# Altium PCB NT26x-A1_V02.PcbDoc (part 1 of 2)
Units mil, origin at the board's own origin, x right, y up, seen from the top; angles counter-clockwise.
Board outline 1026.77 x 2401.57 mil, 4 copper layers (Top Layer 1, GND2, POWER3, Bottom Layer 4), stack 61.855 mil thick; 87 components, 81 nets, 679 pads, 247 vias.
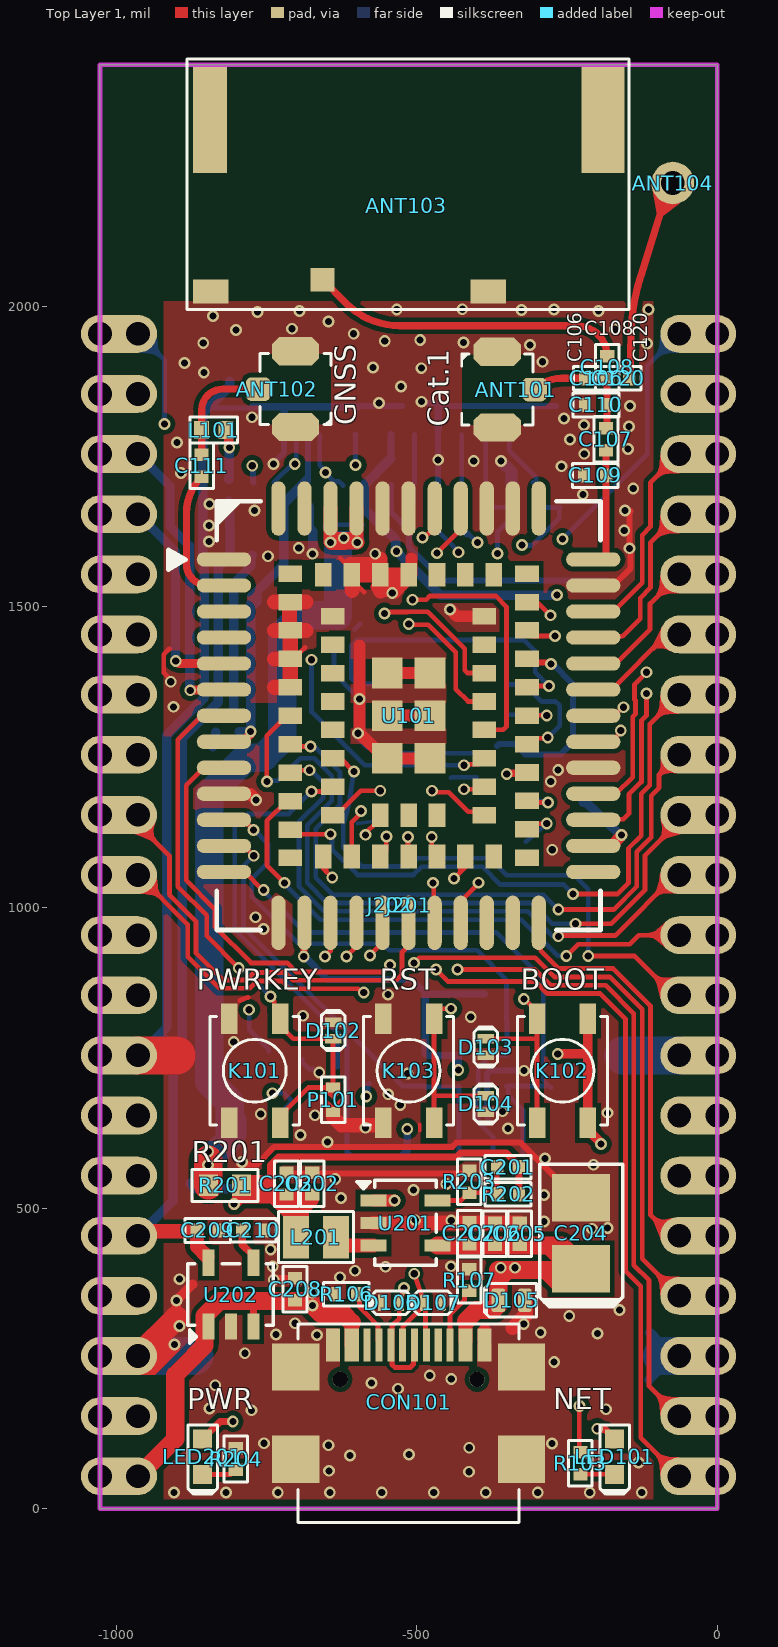
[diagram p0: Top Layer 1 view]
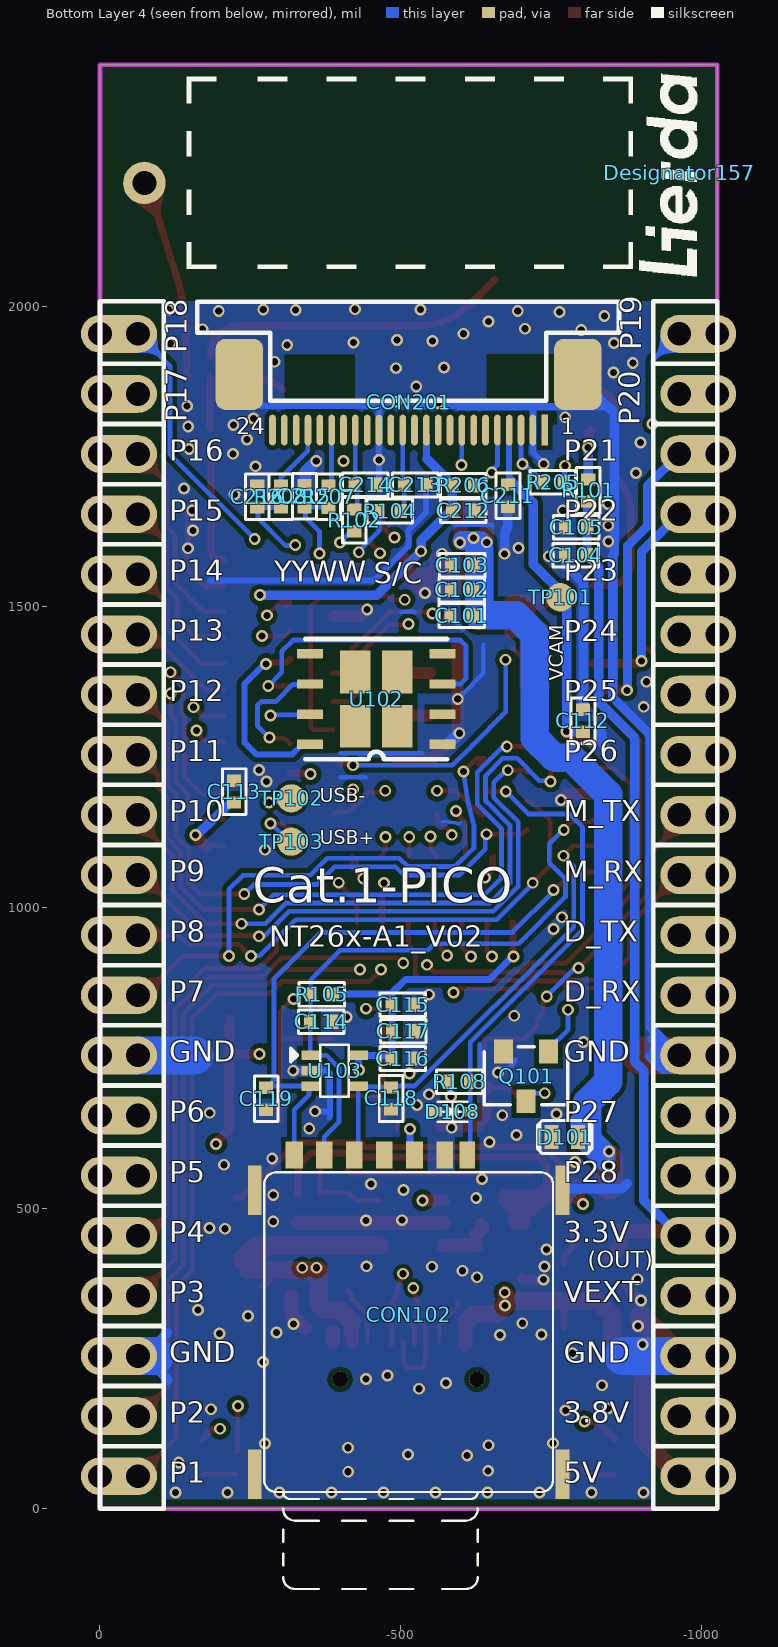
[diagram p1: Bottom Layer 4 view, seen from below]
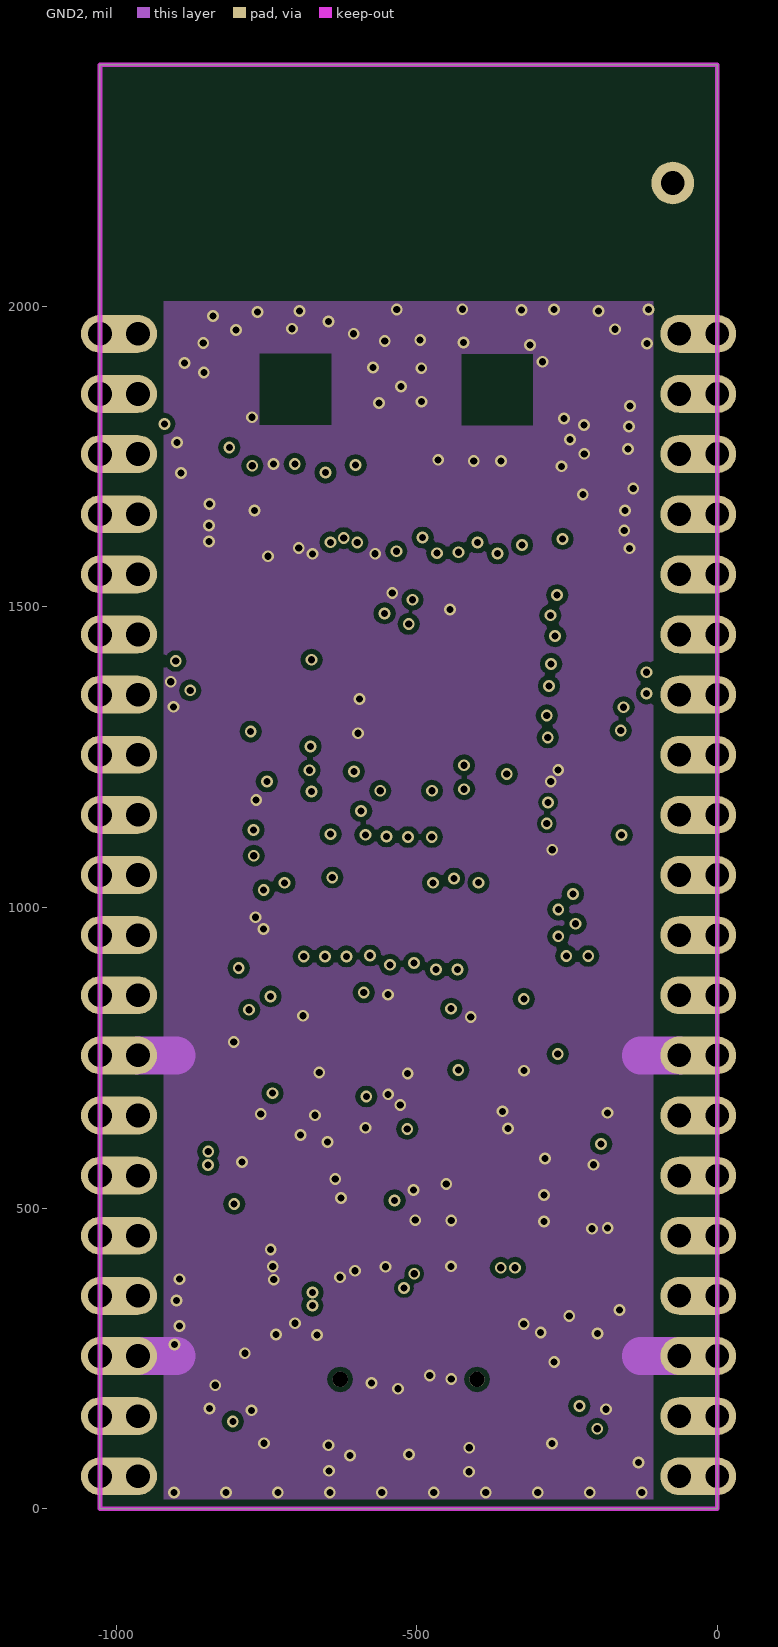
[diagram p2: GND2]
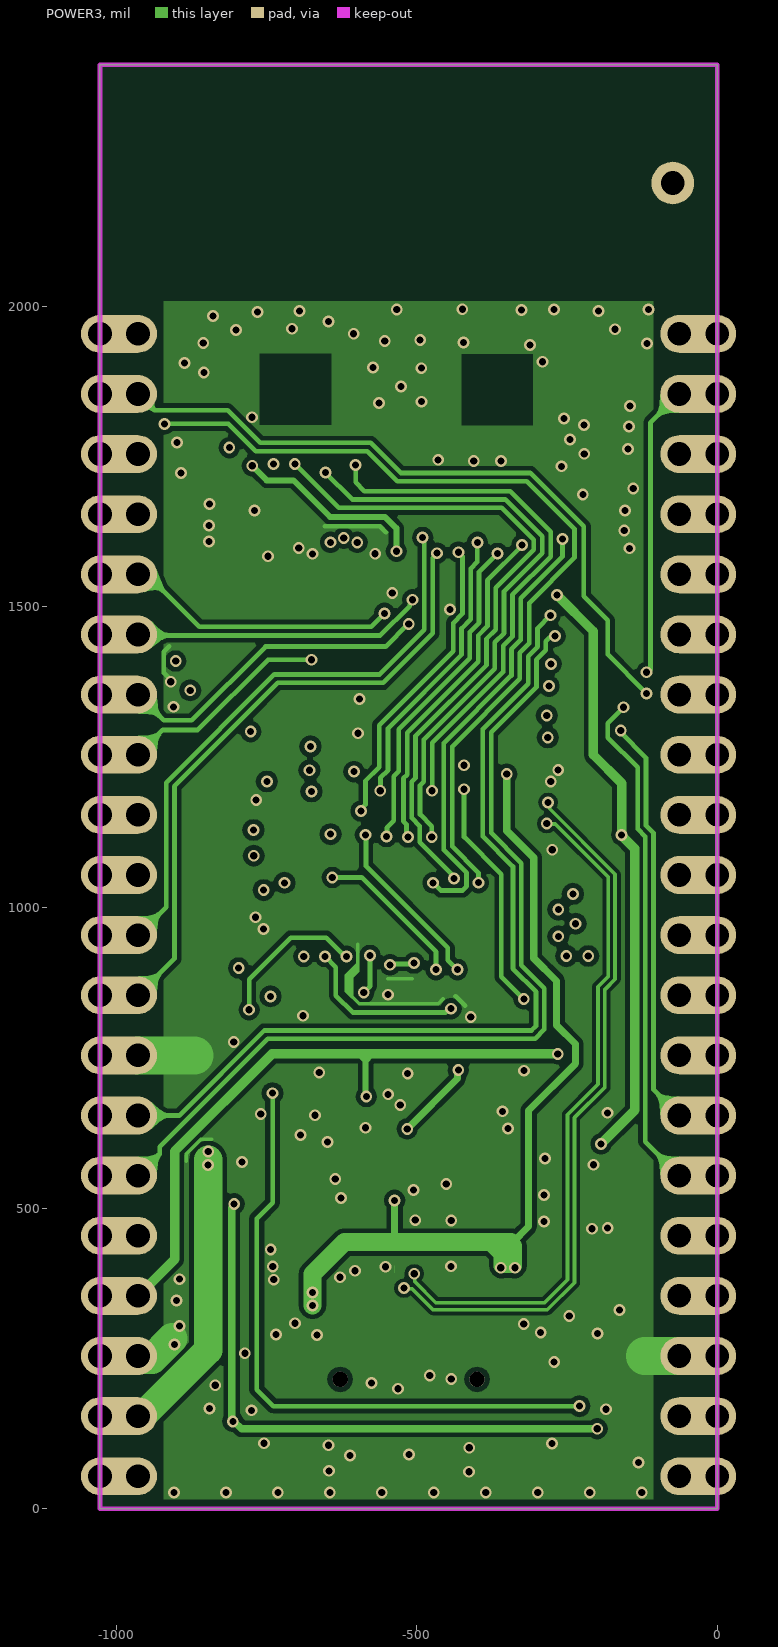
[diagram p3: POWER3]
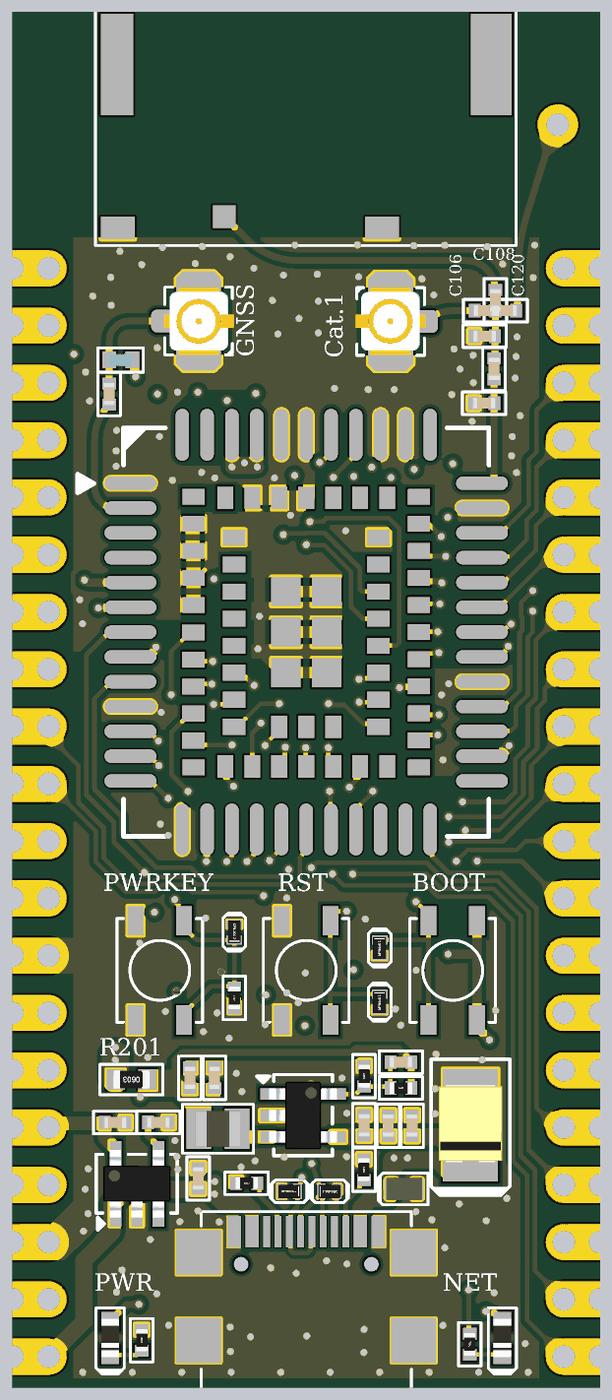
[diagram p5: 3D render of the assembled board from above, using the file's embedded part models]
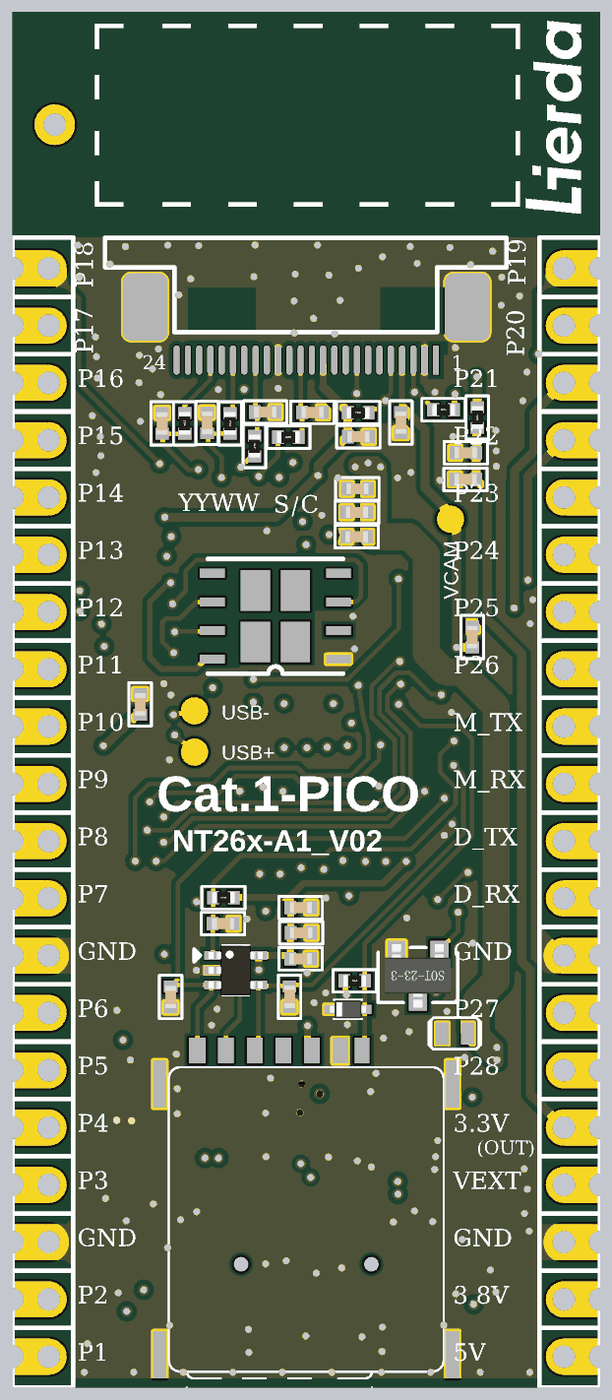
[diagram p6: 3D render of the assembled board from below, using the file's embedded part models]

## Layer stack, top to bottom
Top Solder: solder mask 0.4, Solder Resist, Dk 3.5
Top Layer 1: signal copper 1.378
Dielectric 2: prepreg 8.4646, PP-006, Dk 4.1
GND2: signal copper 1.4
Dielectric 1: dielectric 39.3701, FR-4, Dk 4.8
POWER3: signal copper 1.4
Dielectric 3: prepreg 8.4646, PP-006, Dk 4.1
Bottom Layer 4: signal copper 1.378
Bottom Solder: solder mask 0.4, Solder Resist, Dk 3.5

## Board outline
0,2401.57 -1026.77,2401.57 -1026.77,0 0,0

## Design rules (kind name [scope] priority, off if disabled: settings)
Clearance Clearance_RF [InNetClass('RF')] p1: gap=8 ignorepadtopadclearanceinfootprint=FALSE
Clearance Clearance_diff [InDifferentialPair('usb')] p2: gap=5.5 ignorepadtopadclearanceinfootprint=FALSE except(6: Arc-Fill Arc-Poly Arc-Region Track-Fill Track-Poly Track-Region SMDPad-Fill SMDPad-Poly SMDPad-Region THPad-Fill THPad-Poly THPad-Region Via-Fill Via-Poly Via-Region Fill-Fill Fill-Poly Fill-Region Poly-Poly Poly-Region Region-Region)
Clearance Clearance_via [IsVia vs IsVia] p3: gap=15.75 ignorepadtopadclearanceinfootprint=FALSE
Clearance Clearance_keepout [IsKeepOut] p4: gap=11.81 ignorepadtopadclearanceinfootprint=FALSE
Clearance Clearance_polygon [InPolygon] p5: gap=8 ignorepadtopadclearanceinfootprint=FALSE
Clearance [All] p6: gap=5.98 ignorepadtopadclearanceinfootprint=FALSE except(8: Arc-Fill Arc-Poly Arc-Region Track-Fill Track-Poly Track-Region SMDPad-Fill SMDPad-Poly SMDPad-Region THPad-Fill THPad-Poly THPad-Region Via-Fill Via-Poly Via-Region Fill-Fill Fill-Poly Fill-Region Poly-Poly Poly-Region Region-Region)
DiffPairsRouting [All] p1: maxlimit=5.5 minlimit=5.5 mostfreqgap=5.5 toplayer_minwidth=8 toplayer_maxwidth=8 toplayer_prefwidth=8 midlayer1_minwidth=6 midlayer1_maxwidth=6 midlayer1_prefwidth=6 midlayer2_minwidth=6 midlayer2_maxwidth=6 midlayer2_prefwidth=6 bottomlayer_minwidth=8 bottomlayer_maxwidth=8 bottomlayer_prefwidth=8 maxuncoupledlength=500
HoleSize [All] p1: absolutevalues=TRUE maxlimit=196.85 minlimit=1 maxpercent=80.000 minpercent=20.000
HoleToHoleClearance [All] p1: gap=0 allowstackedmicrovias=TRUE
MinimumSolderMaskSliver [All] p1: minsoldermaskwidth=0
PolygonConnect [All] p1: thpad.connectstyle=Relief thpad.reliefconductorwidth=15 thpad.reliefentries=4 thpad.polygonreliefangle="90 Angle" thpad.airgapwidth=10 smdpad.connectstyle=Direct smdpad.reliefconductorwidth=10 smdpad.reliefentries=4 smdpad.polygonreliefangle="90 Angle" smdpad.airgapwidth=10 via.connectstyle=Direct via.reliefconductorwidth=10 via.reliefentries=4 via.polygonreliefangle="90 Angle" via.airgapwidth=10
RoutingVias [All] p1: holewidth=11.81 width=19.68 viastyle="Through Hole" minholewidth=11.81 minwidth=19.68 maxholewidth=118.11 maxwidth=196.85
SilkToSilkClearance [All] p1: silktosilkclearance=0
SilkToSolderMaskClearance [IsPad] p1: minsilkscreentomaskgap=0 clearancetoexposedcopper=TRUE
SolderMaskExpansion [All] p1: expansion=4
Width [All] p1: maxlimit=196.85 minlimit=5.98 preferedwidth=10
24 further rules are at their usual default settings.

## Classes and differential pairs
net class CAM: CAM_I2C_SCL CAM_I2C_SDA CAM_MCLK CAM_PWDN CAM_SPI_CLK CAM_SPI_D0 CAM_SPI_D1
net class RF: NetANT101_1 NetANT102_1 NetANT103_1 NetANT104_1 NetC106_1 NetC107_2 NetC111_2
component class 02_Peripheral: C201 C202 C203 C204 C205 C206 C207 C208 C209 C210 C211 C212 C213 C214 C215 C216 CON201 J201 J202 L201 LED201 R201 R202 R203 R204 R205 R206 R207 R208 U201 U202
component class 01_NT26FCNB30: ANT101 ANT102 ANT103 ANT104 C101 C102 C103 C104 C105 C106 C107 C108 C109 C110 C111 C112 C113 C114 C115 C116 C117 C118 C119 C120 CON101 CON102 D101 D102 D103 D104 D105 D106 D107 D108 K101 K102 K103 L101 LED101 P101 Q101 R101 R102 R103 R104 R105 R106 R107 R108 TP101 TP102 TP103 U101 U102 U103
differential pair usb: +USB_DN -USB_DP

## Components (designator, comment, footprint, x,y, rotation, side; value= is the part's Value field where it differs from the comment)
ANT101 "IPEX-1" IPX_U.FL-R-SMT-1 -366.35,1861.57 r180 top
ANT102 "IPEX-1" IPX_U.FL-R-SMT-1 -701.09,1861.57 r0 top
ANT103 "PCB天线" ANT -513.39,2201.56 r0 top locked
ANT104 "弹簧天线" ANT104 -74.02,2204.72 r270 top locked
C101 "10uF/10V" 0402C_0.4D -601.52,1485.43 r180 bottom
C102 "0.1uF" 0402C_0.4D -602.08,1528.05 r180 bottom
C103 "33pF" 0402C_0.4D -602.67,1568.98 r180 bottom
C104 "1uF/16V" 0402C_0.4D -791.64,1585.56 r180 bottom
C105 "100pF" 0402C_0.4D -792.1,1632.07 r180 bottom
C106 "NC" 0402C_0.4D -201.22,1879.99 r180 top
C107 "33pF" 0402C_0.4D -185.18,1778.35 r270 top
C108 "NC" 0402C_0.4D -183.02,1898.2 r270 top
C109 "NC" 0402C_0.4D -202.74,1718.44 r0 top
C110 "NC" 0402C_0.4D -201.78,1835.65 r0 top
C111 "33pF" 0402C_0.4D -857.58,1734.5 r270 top
C112 "1uF/16V" 0402C_0.4D -803.34,1310.21 r270 bottom
C113 "1uF/16V" 0402C_0.4D -223.24,1192.74 r270 bottom
C114 "33pF" 0402C_0.4D -368.1,809.93 r0 bottom
C115 "1uF/10V" 0402C_0.4D -503.84,838.01 r0 bottom
C116 "0.1uF" 0402C_0.4D -503.39,748.64 r0 bottom
C117 "33pF" 0402C_0.4D -504.44,793.9 r0 bottom
C118 "33pF" 0402C_0.4D -484.25,682.26 r90 bottom
C119 "33pF" 0402C_0.4D -276.42,681.79 r90 bottom
C120 "33pF" 0402C_0.4D -164.81,1879.99 r0 top
C201 "22pF" 0402C_0.4D -348.1,568.09 r0 top
C202 "0.1uF" 0402C_0.4D -673.72,540.72 r270 top
C203 "10uF/10V" 0402C_0.4D -716.6,540.72 r270 top
C204 "CAP-P" 3528-TB -226.46,457.94 r270 top
C205 "10uF/10V" 0402C_0.4D -328.56,457.23 r270 top
C206 "1uF/16V" 0402C_0.4D -369.91,457.23 r270 top
C207 "0.1uF" 0402C_0.4D -412.23,458 r270 top
C208 "1uF/16V" 0402C_0.4D -702.2,365.14 r270 top
C209 "1uF/16V" 0402C_0.4D -847.22,462.72 r180 top
C210 "0.01uF" 0402C_0.4D -771.78,462.86 r180 top
C211 "1uF" 0402C_0.4D -678.68,1684.65 r270 bottom
C212 "1uF" 0402C_0.4D -604.39,1659.93 r180 bottom
C213 "NC" 0402C_0.4D -524.33,1702.63 r0 bottom
C214 "NC" 0402C_0.4D -441.6,1703.07 r0 bottom
C215 "NC" 0402C_0.4D -340.12,1684.04 r270 bottom
C216 "NC" 0402C_0.4D -261.69,1683.3 r270 bottom
CON101 "USB-TYPE C-12P" "TYPEC _6PIN板" -513.39,177.17 r0 top locked
CON102 "nano-SIM卡座" SIM-MUP-C7801 -513.39,322.83 r180 bottom locked
CON201 "FPC-24" 0.5S-3S-24PWB -513.39,1840.17 r0 bottom locked
D101 "NC" UDFN2(1610)-NP -773.09,618.09 r0 bottom
D102 "TVS" DFN1006-NP#1 -638.96,795.31 r90 top
D103 "TVS" DFN1006-NP#1 -385.13,767.67 r270 top
D104 "TVS" DFN1006-NP#1 -385.13,673.12 r270 top
D105 "DIODE-TVS" UDFN2(1610) -342.12,346.69 r0 top
D106 "DIODE-2TVS-2" DFN1006-NP#1 -542.6,342.66 r180 top
D107 "DIODE-2TVS-2" DFN1006-NP#2 -472.71,342.49 r0 top
D108 "TVS/5V" SOD-523-NP -586.26,660.36 r180 bottom
Designator157 "Comment" LOGO -963.39,2221.57 r90 bottom
J201 "CON_PICO" J201_半孔与排针 -31.69,53.94 r180 top locked
J202 "CON_PICO" J202_半孔与排针 -1026.77,1953.94 r180 top locked
K101 "1414000735" TS3443-0253B -769.29,728.35 r90 top locked
K102 "1414000735" TS3443-0253B -257.48,728.35 r90 top locked
K103 "1414000735" TS3443-0253B -513.39,728.35 r90 top locked
L101 "56nH" 0402LX_0.4D -837.4,1793.92 r0 top
L201 "1uH" 0806L_0.6D -667.53,451.77 r180 top
LED101 "LED绿/25mA" D0603 -170.87,86.61 r90 top
LED201 "LED红/25mA" D0603 -855.91,86.61 r90 top
P101 "PWRKEY" 0402R_0.4D_JP -638.96,680.18 r270 top
Q101 "DTC143XCA" SOT-23-3A -708.63,719 r90 bottom
R101 "10R" 0402R_0.4D -812.28,1693.44 r270 bottom
R102 "22R" 0402R_0.4D -422.93,1643.58 r270 bottom
R103 "1K" 0402R_0.4D -227.75,75.7 r90 top
R104 "22R" 0402R_0.4D -482.21,1659.2 r0 bottom
R105 "NC" 0402R_0.4D -368.81,855.32 r180 bottom
R106 "5.1K" 0402R_0.4D -617.41,356.7 r0 top
R107 "5.1K" 0402R_0.4D -412.54,380.36 r270 top
R108 "NC" 0402R_0.4D -597.98,709.91 r180 bottom
R201 "0R" 0603R_0.6D -818.69,537.73 r180 top
R202 "118K" 0402R_0.4D -348.05,523.08 r0 top
R203 "22.1K" 0402R_0.4D -412.34,543.61 r90 top
R204 "1K" 0402R_0.4D -800.79,82.68 r90 top
R205 "4.7K" 0402R_0.4D -753.33,1706.98 r180 bottom
R206 "4.7K" 0402R_0.4D -604.21,1701.84 r0 bottom
R207 "22R" 0402R_0.4D -380.3,1683.1 r90 bottom
R208 "22R" 0402R_0.4D -300.97,1683.3 r90 bottom
TP101 "CAM_VDD" test#1 -765.46,1515.97 r270 bottom
TP102 "USB_DN" test#1 -318.2,1181.4 r180 bottom
TP103 "USB_DP" test#2 -304.88,1109.37 r180 bottom
U101 "NT26F Y0A-P" LSDWNTC-LY04095005_mood -513.39,1318.9 r0 top locked
U102 "NC" DFN8(1.27)-6X5 -459.64,1346.57 r0 bottom
U103 "NSQA6V8AW5T2G" SOT-323-5 -390.33,728.47 r0 bottom
U201 "ETA3417S2F" SOT-23-5P -518.8,475.08 r180 top
U202 "SGM2036-XYN5G/TR" SOT-23-5P -809.05,355.9 r270 top

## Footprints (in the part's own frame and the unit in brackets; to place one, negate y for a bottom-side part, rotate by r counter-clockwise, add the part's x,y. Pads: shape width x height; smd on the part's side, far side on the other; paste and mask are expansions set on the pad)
0.5S-3S-24PWB [mm]
  rrect40% 2x3 smd mask+0.075: 0(-7.15,-1.175) 0(7.15,-1.175)
  rect 0.28x1.3 smd mask+0.051: 1(-5.75,1.175)
  oval 0.28x1.3 smd mask+0.051: 2(-5.25,1.175) 3(-4.75,1.175) 4(-4.25,1.175) 5(-3.75,1.175) 6(-3.25,1.175) 7(-2.75,1.175) 8(-2.25,1.175) 9(-1.75,1.175) 10(-1.25,1.175) 11(-0.75,1.175) 12(-0.25,1.175) 13(0.25,1.175) 14(0.75,1.175) 15(1.25,1.175) 16(1.75,1.175) 17(2.25,1.175) 18(2.75,1.175) 19(3.25,1.175) 20(3.75,1.175) 21(4.25,1.175) 22(4.75,1.175) 23(5.25,1.175) 24(5.75,1.175)
  silkscreen extent -8.89,-4.24 8.93,-0.06, body extent -9.15,-4.07 9.15,0.63, height 2.05
0402C_0.4D [mm]
  rect 0.525x0.6 smd: 1(-0.463,0) 2(0.463,0)
  silkscreen extent -0.96,-0.5 0.96,0.5, body extent -0.5,-0.25 0.5,0.25, height 0.48
0402LX_0.4D [mm] "线绕电感"
  rect 0.625x0.75 smd: 1(-0.513,0) 2(0.513,0)
  Top Layer 1 pour cut-out: -0.2,-0.478 -0.2,0.478 0.2,0.478 0.2,-0.478
  silkscreen extent -1.01,-0.55 1,0.54, body extent -0.5,-0.3 0.5,0.3, height 0.51
0402R_0.4D [mm]
  rect 0.525x0.6 smd: 1(-0.463,0) 2(0.463,0)
  silkscreen extent -0.96,-0.5 0.96,0.5, body extent -0.5,-0.25 0.5,0.25, height 0.36
0402R_0.4D_JP [mm]
  rect 0.425x0.6 smd mask+0.05: 1(-0.513,0) 2(0.513,0)
  Top Layer 1 region: 0,0 -0.3,0.3 -0.725,0.3 -0.725,-0.3 -0.3,-0.3
  Top Layer 1 region: -0.05,0.3 0.25,0 -0.05,-0.3 0.725,-0.3 0.725,0.3
  silkscreen extent -0.96,-0.5 0.96,0.5, body extent -0.5,-0.25 0.5,0.25, height 0.36
0603R_0.6D [mm]
  rect 0.8x0.9 smd: 1(-0.7,0) 2(0.7,0)
  silkscreen extent -1.4,-0.67 1.4,0.67, body extent -0.8,-0.4 0.8,0.4, height 0.46
0806L_0.6D [mm]
  rect 1.1x1.8 smd: 1(-0.85,0) 2(0.85,0)
  Top Layer 1 pour cut-out: -0.3,-0.9 -0.3,0.9 0.301,0.9 0.301,-0.9
  silkscreen extent -1.58,-1.08 1.58,1.08, body extent -1,-0.8 1,0.8, height 1
3528-TB [mm]
  rect 2x2.45 smd: 1(1.5,0) 2(-1.5,0)
  silkscreen extent -2.93,-1.75 3.1,1.75, body extent -1.82,-1.4 1.67,1.4, height 1.91
ANT [mm]
  rect 1x1 smd: 1(-3.64,-4)
  rect 1.5x1 smd: 2(-8.36,-4.5) 2(3.36,-4.5)
  rect 1.43x4.5 smd: 3(-8.395,2.75)
  rect 1.8x4.5 smd: 4(8.21,2.75)
  silkscreen extent -9.35,-5.27 9.31,5.32
ANT104 [mm]
  round 1.8 hole 1: 1(0,0)
D0603 [mm]
  rect 0.8x0.8 smd: A(0.75,0) K(-0.75,0)
  silkscreen extent -1.59,-0.63 1.33,0.63, body extent -0.85,-0.4 0.85,0.4, height 0.56
DFN8(1.27)-6X5 [mm]
  rect 1.3x1.8 smd: 0(-0.889,-1.143) 0(-0.889,1.143) 0(0.889,-1.143) 0(0.889,1.143)
  rect 1.1x0.4 smd: 1(-2.8,1.905) 2(-2.8,0.635) 3(-2.8,-0.635) 4(-2.8,-1.905) 5(2.8,-1.905) 6(2.8,-0.635) 7(2.8,0.635) 8(2.8,1.905)
  round 0.3 on Mech15 mask+0: ""(-2.8,1.905)
  rect 0.6x0.4 on Mech1 mask+0: ""(-2.7,-1.905) ""(-2.7,-0.635) ""(-2.7,0.635) ""(-2.7,1.905) ""(2.7,-1.905) ""(2.7,-0.635) ""(2.7,0.635) ""(2.7,1.905)
  round 0.3 on Mech1 mask+0: ""(0,0) ""(0,0)
  rect 3.4x4.2 on Mech1 mask+0: ""(0,0)
  silkscreen extent -3,-2.54 3,2.54
DFN1006-NP#1 [mm]
  rect 0.4x0.7 smd mask+0.051: A(0.35,0) K(-0.35,0)
  rect 0.25x0.5 on Mech1: ""(-0.325,0) ""(0.325,0)
  silkscreen extent -0.85,-0.5 0.85,0.5, body extent -0.5,-0.3 0.5,0.3, height 0.51
DFN1006-NP#2 [mm]
  rrect40% 0.4x0.7 smd mask+0.051: A(0.35,0) K(-0.35,0)
  rect 0.25x0.5 on Mech1: ""(-0.325,0) ""(0.325,0)
  silkscreen extent -0.85,-0.5 0.85,0.5, body extent -0.5,-0.3 0.5,0.3, height 0.51
IPX_U.FL-R-SMT-1 [mm]
  rrect50% 1.05x1 smd: 1(-1.585,0.01)
  oct 2x1.2 smd: 2(-0.01,-1.59) 3(-0.01,1.61)
  Multi-Layer pour cut-out: 1.49,1.51 1.49,-1.49 -1.51,-1.49 -1.51,1.51
  silkscreen extent -1.51,-1.49 1.49,1.51, body extent -1.55,-1.5 1.55,1.5, height 1.25
J201_半孔与排针 [mm]
  round 1.6 hole 1: 1(-0.805,0) 1(0.805,0) 2(-0.805,-2.54) 2(0.805,-2.54) 3(-0.805,-5.08) 3(0.805,-5.08) 4(-0.805,-7.62) 4(0.805,-7.62) 5(-0.805,-10.16) 5(0.805,-10.16) 6(-0.805,-12.7) 6(0.805,-12.7) 7(-0.805,-15.24) 7(0.805,-15.24) 8(-0.805,-17.78) 8(0.805,-17.78) 9(-0.805,-20.32) 9(0.805,-20.32) 10(-0.805,-22.86) 10(0.805,-22.86) 11(-0.805,-25.4) 11(0.805,-25.4) 12(-0.805,-27.94) 12(0.805,-27.94) 13(-0.805,-30.48) 13(0.805,-30.48) 14(-0.805,-33.02) 14(0.805,-33.02) 15(-0.805,-35.56) 15(0.805,-35.56) 16(-0.805,-38.1) 16(0.805,-38.1) 17(-0.805,-40.64) 17(0.805,-40.64) 18(-0.805,-43.18) 18(0.805,-43.18) 19(-0.805,-45.72) 19(0.805,-45.72) 20(-0.805,-48.26) 20(0.805,-48.26)
  rect 1.6x1.6 all layers, no hole: 1(0,0) 2(0,-2.54) 3(0,-5.08) 4(0,-7.62) 5(0,-10.16) 6(0,-12.7) 7(0,-15.24) 8(0,-17.78) 9(0,-20.32) 10(0,-22.86) 11(0,-25.4) 12(0,-27.94) 13(0,-30.48) 14(0,-33.02) 15(0,-35.56) 16(0,-38.1) 17(0,-40.64) 18(0,-43.18) 19(0,-45.72) 20(0,-48.26)
  round 1.6 on Mech1: 21(23.665,-48.26) 21(25.275,-48.26) 22(23.665,-45.72) 22(25.275,-45.72) 23(23.665,-43.18) 23(25.275,-43.18) 24(23.665,-40.64) 24(25.275,-40.64) 25(23.665,-38.1) 25(25.275,-38.1) 26(23.665,-35.56) 26(25.275,-35.56) 27(23.665,-33.02) 27(25.275,-33.02) 28(23.665,-30.48) 28(25.275,-30.48) 29(23.665,-27.94) 29(25.275,-27.94) 30(23.665,-25.4) 30(25.275,-25.4) 31(23.665,-22.86) 31(25.275,-22.86) 32(23.665,-20.32) 32(25.275,-20.32) 33(23.665,-17.78) 33(25.275,-17.78) 34(23.665,-15.24) 34(25.275,-15.24) 35(23.665,-12.7) 35(25.275,-12.7) 36(23.665,-10.16) 36(25.275,-10.16) 37(23.665,-7.62) 37(25.275,-7.62) 38(23.665,-5.08) 38(25.275,-5.08) 39(23.665,-2.54) 39(25.275,-2.54) 40(23.665,0) 40(25.275,0)
  rect 1.6x1.6 on Mech1: 21(24.47,-48.26) 22(24.47,-45.72) 23(24.47,-43.18) 24(24.47,-40.64) 25(24.47,-38.1) 26(24.47,-35.56) 27(24.47,-33.02) 28(24.47,-30.48) 29(24.47,-27.94) 30(24.47,-25.4) 31(24.47,-22.86) 32(24.47,-20.32) 33(24.47,-17.78) 34(24.47,-15.24) 35(24.47,-12.7) 36(24.47,-10.16) 37(24.47,-7.62) 38(24.47,-5.08) 39(24.47,-2.54) 40(24.47,0)
J202_半孔与排针 [mm]
  round 1.6 on Mech1: 1(-24.47,48.26)
  round 1.6 hole 1: 21(-1.61,0) 21(0,0) 22(-1.61,2.54) 22(0,2.54) 23(-1.61,5.08) 23(0,5.08) 24(-1.61,7.62) 24(0,7.62) 25(-1.61,10.16) 25(0,10.16) 26(-1.61,12.7) 26(0,12.7) 27(-1.61,15.24) 27(0,15.24) 28(-1.61,17.78) 28(0,17.78) 29(-1.61,20.32) 29(0,20.32) 30(-1.61,22.86) 30(0,22.86) 31(-1.61,25.4) 31(0,25.4) 32(-1.61,27.94) 32(0,27.94) 33(-1.61,30.48) 33(0,30.48) 34(-1.61,33.02) 34(0,33.02) 35(-1.61,35.56) 35(0,35.56) 36(-1.61,38.1) 36(0,38.1) 37(-1.61,40.64) 37(0,40.64) 38(-1.61,43.18) 38(0,43.18) 39(-1.61,45.72) 39(0,45.72) 40(-1.61,48.26) 40(0,48.26)
  rect 1.6x1.6 all layers, no hole: 21(-0.805,0) 22(-0.805,2.54) 23(-0.805,5.08) 24(-0.805,7.62) 25(-0.805,10.16) 26(-0.805,12.7) 27(-0.805,15.24) 28(-0.805,17.78) 29(-0.805,20.32) 30(-0.805,22.86) 31(-0.805,25.4) 32(-0.805,27.94) 33(-0.805,30.48) 34(-0.805,33.02) 35(-0.805,35.56) 36(-0.805,38.1) 37(-0.805,40.64) 38(-0.805,43.18) 39(-0.805,45.72) 40(-0.805,48.26)
LOGO [mil]
  silkscreen extent -172,-30 164,66
LSDWNTC-LY04095005_mood [mm]
  oval 2.3x0.6 smd mask+0.076: 1(-7.8,6.6) 2(-7.8,5.5) 3(-7.8,4.4) 4(-7.8,3.3) 5(-7.8,2.2) 6(-7.8,1.1) 7(-7.8,0) 8(-7.8,-1.1) 9(-7.8,-2.2) 10(-7.8,-3.3) 11(-7.8,-4.4) 12(-7.8,-5.5) 13(-7.8,-6.6) 23(7.8,-6.6) 24(7.8,-5.5) 25(7.8,-4.4) 26(7.8,-3.3) 27(7.8,-2.2) 28(7.8,-1.1) 29(7.8,0) 30(7.8,1.1) 31(7.8,2.2) 32(7.8,3.3) 33(7.8,4.4) 34(7.8,5.5) 35(7.8,6.6)
  oval 1.5x0.6 on Mech1 mask+0.076: 1(-7.4,6.6) 2(-7.4,5.5) 3(-7.4,4.4) 4(-7.4,3.3) 5(-7.4,2.2) 6(-7.4,1.1) 7(-7.4,0) 8(-7.4,-1.1) 9(-7.4,-2.2) 10(-7.4,-3.3) 11(-7.4,-4.4) 12(-7.4,-5.5) 13(-7.4,-6.6) 23(7.4,-6.6) 24(7.4,-5.5) 25(7.4,-4.4) 26(7.4,-3.3) 27(7.4,-2.2) 28(7.4,-1.1) 29(7.4,0) 30(7.4,1.1) 31(7.4,2.2) 32(7.4,3.3) 33(7.4,4.4) 34(7.4,5.5) 35(7.4,6.6)
  oval 0.6x2.3 smd mask+0.076: 14(-4.4,-8.75) 15(-3.3,-8.75) 16(-2.2,-8.75) 17(-1.1,-8.75) 18(0,-8.75) 19(1.1,-8.75) 20(2.2,-8.75) 21(3.3,-8.75) 22(4.4,-8.75) 36(4.4,8.75) 37(3.3,8.75) 38(2.2,8.75) 39(1.1,8.75) 40(0,8.75) 41(-1.1,8.75) 42(-2.2,8.75) 43(-3.3,8.75) 44(-4.4,8.75) 95(-5.5,-8.75) 96(5.5,-8.75) 97(5.5,8.75) 98(-5.5,8.75)
  oval 0.6x1.5 on Mech1 mask+0.076: 14(-4.4,-8.35) 15(-3.3,-8.35) 16(-2.2,-8.35) 17(-1.1,-8.35) 18(0,-8.35) 19(1.1,-8.35) 20(2.2,-8.35) 21(3.3,-8.35) 22(4.4,-8.35) 36(4.4,8.35) 37(3.3,8.35) 38(2.2,8.35) 39(1.1,8.35) 40(0,8.35) 41(-1.1,8.35) 42(-2.2,8.35) 43(-3.3,8.35) 44(-4.4,8.35) 95(-5.5,-8.35) 96(5.5,-8.35) 97(5.5,8.35) 98(-5.5,8.35)
  rect 1x0.7 smd: 45(-5,4.8) 46(-5,3.6) 47(-5,2.4) 48(-5,1.2) 49(-5.003,-0.011) 50(-5.003,-1.211) 51(-5.003,-2.411) 52(-5.003,-3.611) 53(-5.003,-4.811) 59(5,-4.8) 60(5,-3.6) 61(5,-2.4) 62(5,-1.2) 63(5,0) 64(5,1.2) 65(5,2.4) 66(5,3.6) 67(5,4.8) 73(-3.2,4.2) 74(-3.2,3) 75(-3.2,1.8) 76(-3.2,0.6) 77(-3.2,-0.6) 78(-3.2,-1.8) 79(-3.2,-3) 80(-3.2,-4.2) 81(3.2,-4.2) 82(3.2,-3) 83(3.2,-1.8) 84(3.2,-0.6) 85(3.2,0.6) 86(3.2,1.8) 87(3.2,3) 88(3.2,4.2) 99(-5,6) 100(-5,-6) 103(5,-6) 104(5,6)
  rect 1x0.7 on Mech1: 45(-5,4.8) 46(-5,3.6) 47(-5,2.4) 48(-5,1.2) 49(-5.003,-0.011) 50(-5.003,-1.211) 51(-5.003,-2.411) 52(-5.003,-3.611) 53(-5.003,-4.811) 59(5,-4.8) 60(5,-3.6) 61(5,-2.4) 62(5,-1.2) 63(5,0) 64(5,1.2) 65(5,2.4) 66(5,3.6) 67(5,4.8) 73(-3.2,4.2) 74(-3.2,3) 75(-3.2,1.8) 76(-3.2,0.6) 77(-3.2,-0.6) 78(-3.2,-1.8) 79(-3.2,-3) 80(-3.2,-4.2) 81(3.2,-4.2) 82(3.2,-3) 83(3.2,-1.8) 84(3.2,-0.6) 85(3.2,0.6) 86(3.2,1.8) 87(3.2,3) 88(3.2,4.2) 99(-5,6) 100(-5,-6) 103(5,-6) 104(5,6)
  rect 0.7x1 smd: 54(-2.4,-5.95) 55(-1.2,-5.95) 56(0,-5.95) 57(1.2,-5.95) 58(2.4,-5.95) 68(2.4,5.95) 69(1.2,5.95) 70(0,5.95) 71(-1.2,5.95) 72(-2.4,5.95) 101(-3.6,-5.95) 102(3.6,-5.95) 105(3.6,5.95) 106(-3.6,5.95) 107(-1.2,-4.2) 108(0,-4.2) 109(1.2,-4.2)
  rect 0.7x1 on Mech1: 54(-2.4,-5.95) 55(-1.2,-5.95) 56(0,-5.95) 57(1.2,-5.95) 58(2.4,-5.95) 68(2.4,5.95) 69(1.2,5.95) 70(0,5.95) 71(-1.2,5.95) 72(-2.4,5.95) 101(-3.6,-5.95) 102(3.6,-5.95) 105(3.6,5.95) 106(-3.6,5.95) 107(-1.2,-4.2) 108(0,-4.2) 109(1.2,-4.2)
  rect 1.3x1.3 smd: 89(-0.9,1.8) 90(-0.9,0) 91(-0.9,-1.8) 92(0.9,-1.8) 93(0.9,0) 94(0.9,1.8)
  rect 1.3x1.3 on Mech1: 89(-0.9,1.8) 90(-0.9,0) 91(-0.9,-1.8) 92(0.9,-1.8) 93(0.9,0) 94(0.9,1.8)
  round 0.8 on Mech1: ""(5.85,6.95) ""(6.95,7.95)
  silkscreen extent -10.14,-9.06 8.11,9.06
SIM-MUP-C7801 [mm]
  rect 0.58x2.1 smd: 0(-6.5,5.258) 0(-6.5,-6.742) 0(6.5,-6.742) 0(6.5,5.258)
  rect 1.8x2.8 on Mech1: 0(-3.82,-5.743) 0(-1.28,-5.743) 0(1.26,-5.743)
  rect 1.4x2.95 on Mech1: 0(-3.82,0.233) 0(-1.28,0.233) 0(1.26,0.233)
  rect 1.4x2.3 on Mech1: 0(1.26,4.257)
  rect 0.7x1.13 smd: 1(0.25,6.743) 2(-2.29,6.743) 5(1.52,6.743) 6(-1.02,6.743) 7(-3.56,6.743)
  rect 0.75x1.13 smd: 3(-4.83,6.743)
  rect 0.65x1.13 smd: CD(2.47,6.743)
  silkscreen extent -6.1,-11.59 6.1,6.01
SOD-523-NP [mm]
  rect 0.6x0.4 smd: A(0.75,0) K(-0.75,0)
  silkscreen extent -0.63,-0.43 0.63,0.43, body extent -0.8,-0.4 0.8,0.4, height 0.7
SOT-23-3A [mm]
  rect 1x0.8 smd: B(1.05,-0.95) C(-1.05,0) E(1.05,0.95)
  rect 0.55x0.5 on Mech1: ""(-1.025,0) ""(1.025,-0.95) ""(1.025,0.95)
  silkscreen extent -1.19,-1.77 1.25,1.77, body extent -1.41,-1.45 1.41,1.45, height 1.22
SOT-23-5P [mm]
  rect 1.1x0.508 smd: 1(1.35,-0.95) 2(1.35,0) 3(1.35,0.95) 4(-1.35,0.95) 5(-1.35,-0.95)
  silkscreen extent -1.3,-1.81 2.06,1.79, body extent -1.5,-1.5 1.5,1.5, height 1.3
SOT-323-5 [mm]
  rect 0.8x0.4 smd mask+0.051: 1(1,-0.65) 2(1,0) 3(1,0.65) 4(-1,0.65) 5(-1,-0.65)
  silkscreen extent -0.6,-1.1 1.85,1.1, body extent -1.2,-1.1 1.2,1.1, height 1.1
test#1 [mm]
  round 1.2 smd paste-10: 1(0,0)
test#2 [mm]
  round 1.2 smd paste-10: 1(0.338,0)
TS3443-0253B [mm]
  rect 1.3x0.7 smd: 1(-2.2,1.075) 2(2.2,1.075) 3(-2.2,-1.075) 4(2.2,-1.075)
  silkscreen extent -2.3,-1.9 2.3,1.9, body extent -2.2,-1.7 2.2,1.7, height 2.5
"TYPEC _6PIN板" [mm]
  rect 2x2 smd mask+0.064: 0(-4.77,-2.412) 0(-4.77,1.488) 0(4.77,-2.412) 0(4.77,1.488)
  round 0.65 hole 0.65 unplated: 0(-2.89,0.968) 0(2.89,0.968)
  rect 0.6x1.4 smd mask+0.051: A1B12(-3.2,2.413) A4B9(-2.4,2.413) B1A12(3.2,2.413) B4A9(2.4,2.413)
  rect 0.3x1.4 smd mask+0.051: A5(-1.25,2.413) A6(-0.25,2.413) A7(0.25,2.413) A8(1.25,2.413) B5(1.75,2.413) B6(0.75,2.413) B7(-0.75,2.413) B8(-1.75,2.413)
  silkscreen extent -4.67,-5.09 4.67,3.3, body extent -4.5,-4.93 4.5,2.47, height 3.16
UDFN2(1610) [mm]
  rrect40% 0.58x1 smd mask+0.076: A(0.56,0) K(-0.56,0)
  rect 0.4x0.88 on Mech1: ""(-0.55,0) ""(0.55,0)
  silkscreen extent -1.15,-0.7 1.05,0.7, body extent -0.8,-0.5 0.8,0.5, height 0.59
UDFN2(1610)-NP [mm]
  rect 0.58x1 smd mask+0.076: A(0.56,0) K(-0.56,0)
  rect 0.4x0.88 on Mech1: ""(-0.55,0) ""(0.55,0)
  silkscreen extent -1.15,-0.7 1.15,0.7

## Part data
ANT101 ANT102: library part 1416000325, "DC-6GHz"
ANT103: library part "ANT 2P", "PCB/陶瓷/铁件天线"
ANT104: library part 1417001013, "5.0/10.5/0.8"
C101 C203 C205: library part 1405001308, "10uF/10V/20%/X5R"
C102 C116 C202 C207: library part 1405000041, "0.1uF/16V/10%/X7R"
C103 C106 C107 C108 C109 C110 C111 C114 C117 C118 C119 C120 C213 C214 C215 C216: library part 1405000291, "33pF/50V/5%/C0G"
C104 C112 C113 C206 C208 C209: library part 1405004038, "1uF/16V/10%/X5R"
C105: library part 1405000254, "100pF/50V/5%/C0G"
C115 C211 C212: library part 1405001767, "1uF/10V/10%/X5R"
C201: library part 1405000255, "22pF/50V/5%/C0G"
C204: library part 1405001402, "220uF/6.3V/20%/35mΩ"
C210: library part 1405000289, "10nF/50V/10%/X7R"
CON101: library part 1416003448, "USB Type-C"
CON102: library part 1416003211, "Push-Push NANO-SIM Card Connector"
CON201: library part 1416000423, "0.50mm/24PIN"
D101: library part 1409003027, "双向"
D102 D103 D104: library part 1409004149, "1通道"
D105: library part 1409004319, "1通道"
D106 D107: library part 1409004148, "1通道"
D108: library part 1409000207, "ESD保护/双向"
J201 J202: library part 1416002098, "2.54mm/1*20PIN/ֱ"
K101 K102 K103: library part 1416003591, "6*6*7.3"
L101: library part 1404000107, "56nH/2%/200mA/1.17Ω"
L201: library part 1404002051, "1uH/20%/2*1.6*1/2.9A/0.06Ω"
LED101: library part 1409000351, "绿/25mA/112-285mcd"
LED201: library part 1409000426, "红/25mA/54mcd"
P101: library part JP2Q, "短路帽"
Q101: library part 1412002409, "NPN/0.1A/50V/200mW"
R101: library part 1408001194, "10R/1%"
R102 R104 R207 R208: library part 1408001926, "22R/5%"
R103 R204: library part 1408000156, "1K/5%"
R105 R108: library part 1408000158, "10K/5%"
R106 R107: library part 1408001063, "5.1K/5%"
R201: library part 1408000425, "0R/1%"
R202: library part 1408006755, "118K/1%"
R203: library part 1408006226, "22.1K/1%"
R205 R206: library part 1408000467, "4.7K/5%"
TP101 TP102 TP103: library part MARK
U101: library part "NT26F Y0A-P-B01"
U102: library part 180006-03G
U103: library part 1409000217, "双向/7.14V/600W"
U201: library part 1407003604, "2.6-7V/0.6-7V/2.5A/3MHz/Buck"
U202: library part 1407000926, "3.3V/300mA/1.6-5.5V"

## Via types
v1: diameter 19.68, hole 11.81, Top Layer 1 to Bottom Layer 4, tented both sides, 247 vias

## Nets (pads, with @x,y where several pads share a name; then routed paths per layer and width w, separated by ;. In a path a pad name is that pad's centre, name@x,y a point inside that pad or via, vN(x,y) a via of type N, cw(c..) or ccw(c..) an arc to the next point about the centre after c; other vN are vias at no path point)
3.3V: C104.2 C105.2 C209.2 J202.36 R101.2 U202.5 | length 1436.1
  Top Layer 1 w23.62: J202.36@-963.39,453.94 -955.85,461.47 C209.2@-865.43,461.47 ; C209.2@-865.43,462.72 C209.2@-865.43,461.47 ; U202.5@-848.26,418.9 -865.43,436.07 C209.2@-865.43,461.47
  Bottom Layer 4 w15.75: J202.36@-963.39,453.94 -904.8,512.53 -904.8,727.99 -889.71,743.08 -889.71,1281.61 -829.76,1341.56 -829.76,1565.66 C104.2@-809.85,1585.56 ; R101.2@-812.28,1675.23 -811.14,1674.09 C105.2@-811.14,1632.9 ; C104.2@-810.05,1585.76 C105.2@-810.05,1631.81
3.8V: C201.2 C202.2 C203.2 L201.2 LED101.A LED201.A R201.1 R202.2 | length 2069.3
  Top Layer 1 w10: R201.1@-780.77,542.09 -746.97,542.09 ; R201.1@-780.16,550.2 -746.35,550.2 ; R201.1@-779.17,536.25 -745.37,536.25 ; -750.22,543.31 C203.2@-726.31,519.4 ; -746.72,545.34 C203.2@-722.82,521.44
  Top Layer 1 w11.81: LED201.A@-855.91,116.14 -826.78,145.27 v1(-805.72,145.27) ; -742.89,519.6 -742.89,571.66 -729.52,585.03 -433.49,585.03 -426.72,591.79 -351.05,591.79 -334.32,575.06 -334.32,573.99 -329.89,569.57 C201.2@-329.89,568.09 ; R202.2@-329.87,523.11 C201.2@-329.89,568.09 ; v1(-199.67,133) -198.16,131.5 -186.22,131.5 LED101.A@-170.87,116.14
  Top Layer 1 w20: v1(-803.46,507) -796.88,513.57 -796.88,531.98 R201.1@-791.13,537.73
  Top Layer 1 w23.62: -793.98,519.52 -768.34,519.52 ; R201.1@-791.13,537.73 -773,519.6 -742.89,519.6 C202.2@-675.15,519.6 ; -734.03,514.68 -715.9,496.55 ; L201.2@-704.53,476.44 -704.53,513.41 ; -692.33,496.37 -691.08,497.62 ; L201.2@-691.08,474.68 -691.08,497.62 ; -691.08,500.32 -691.08,497.62 ; C202.2@-674.2,514.5 -691.08,497.62
  POWER3 w11.81: v1(-805.72,145.27) -803.59,145.27 -791.33,133 v1(-199.67,133) ; v1@-805.37,147.05 -807.5,149.18 -807.5,500.82 -803.46,504.86 v1(-803.46,507)
ADC0: J201.4 U101.9@-820.47,1232.28 | length 1622.6
  Top Layer 1 w7.87: U101.9@-820.47,1232.28 -853.94,1232.28 -883.39,1202.83 -883.39,1044.94 -835.42,996.97 -835.42,967.63 -775.5,907.71 -715.26,907.71 -700.1,892.56 -556.07,892.56 v1(-544.06,904.57) ; v1@-501.33,907.53 v1(-504.53,907.53) -495.65,916.41 -302.77,916.41 -270.78,884.42 -178.7,884.42 -124.99,830.71 -124.99,415.54 J201.4@-63.39,353.94
  POWER3 w7.87: v1(-544.06,904.57) -542.58,906.05 -506.01,906.05 v1(-504.53,907.53)
ADC1: J201.5 U101.96@-296.85,974.41 | length 678.1
  Top Layer 1 w7.87: U101.96@-296.85,974.41 -293.84,971.4 -293.84,928.17 -263.95,898.28 -172.96,898.28 -111.13,836.45 -111.13,488.62 -76.45,453.94 J201.5@-63.39,453.94
AGPIO4: J202.21 U101.20@-426.77,974.41 | length 1691.6
  Top Layer 1 w7.87: U101.20@-427.14,974.78 -427.14,1009.33 -397.17,1039.3 v1(-397.17,1041.13)
  POWER3 w7.87: v1(-919.2,1804.18) -812.98,1804.18 -767.58,1758.78 -582.24,1758.78 -532.27,1708.81 -316.78,1708.81 -237.51,1629.53 -237.51,1581.57 -312.85,1506.22 -312.85,1439.09 -328.42,1423.52 -328.42,1380.09 -440.93,1267.58 -440.93,1101.42 -397.17,1057.66 v1(-397.17,1041.13)
  Bottom Layer 4 w7.87: J202.21@-963.39,1953.94 -919.2,1909.75 v1(-919.2,1804.18)
AGPIO6: J202.22 U101.25@-206.3,1145.67 | length 1429.3
  Top Layer 1 w7.87: U101.25@-206.3,1145.67 -205.44,1146.52 -156.03,1146.52 -146.96,1155.59 -146.96,1187.96 -126.24,1208.68 -126.24,1310.68 -117.82,1319.11 v1(-117.82,1355.6)
  POWER3 w7.87: J202.22@-963.39,1853.94 -963.02,1853.94 -935.84,1826.76 -814.12,1826.76 -760,1772.64 -576.5,1772.64 -526.53,1722.66 -311.04,1722.66 -222.1,1633.72 -222.1,1517.35 -182.16,1477.4 -182.16,1420.77 -117.82,1356.43 v1(-117.82,1355.6)
AGPIOWU1: J201.2 U101.107@-560.63,1153.54 | length 1413.6
  Top Layer 1 w7.87: v1(-585.22,1120.77) -585.22,1123.05 -566.71,1141.56 -560.63,1141.56 U101.107@-560.63,1153.54 ; v1@-436.22,896.64 v1(-432.28,896.64) -302.91,896.64 -276.83,870.57 -185.87,870.57 -138.85,823.54 -138.85,404.91 -113.51,379.57 -113.51,204.06 -81.39,171.94 -81.39,160.2 -87.65,153.94 J201.2@-63.39,153.94 J201.2@-31.69,153.94
  POWER3 w7.87: v1(-585.22,1120.77) -584.37,1119.92 -584.37,1068.98 -448.17,932.79 -448.17,912.53 v1(-432.28,896.64)
AGPIOWU2: J201.20 U101.19@-470.08,974.41 | length 1326
  Top Layer 1 w7.87: v1(-472.68,1040.94) -471.38,1039.64 -471.38,975.71 U101.19@-470.08,974.41 -467.07,977.42 -467.07,1015.15 U101.19@-465.31,1013.39
  POWER3 w7.87: v1(-472.68,1040.94) -460.05,1028.31 -423.65,1028.31 -416.94,1035.03 -416.94,1057.83 -454.79,1095.68 -454.79,1273.32 -342.28,1385.83 -342.28,1429.26 -326.71,1444.83 -326.71,1514.31 -257.37,1583.65 -257.37,1597.61 v1(-257.37,1612.96) ; J201.20@-62.7,1953.94 J201.20@-31.69,1953.94 J201.20@-47.54,1938.09
  Bottom Layer 4 w7.87: v1(-257.37,1612.96) -116.52,1753.81 -116.52,1900.8 J201.20@-63.39,1953.94
AUX_RXD: J201.7 U101.28@-206.3,1275.59 | length 735.7
  Top Layer 1 w7.87: U101.28@-206.3,1275.59 -175.58,1275.59 -175.58,1275.93 -160.56,1290.95 v1(-160.56,1294.03)
  POWER3 w7.87: v1(-160.56,1294.03) -160.56,1291.04 -118.65,1249.13 -118.65,1136.32 -106.01,1123.68 -106.01,696.56 J201.7@-63.39,653.94
AUX_TXD: J201.6 U101.29@-206.3,1318.9 | length 895.5
  Top Layer 1 w7.87: U101.29@-206.3,1318.9 -171.29,1318.9 -157.29,1332.9 v1(-155.74,1332.9)
  POWER3 w7.87: v1(-155.74,1332.9) -182.14,1306.49 -182.14,1282.49 -132.51,1232.85 -132.51,1130.58 -119.87,1117.94 -119.87,610.42 J201.6@-63.39,553.94
CAM_I2C_SCL: CON201.5 R206.1 U101.57@-466.14,1084.65 | length 1136
  Top Layer 1 w7.87: v1(-474.87,1117.2) -474.87,1093.38 U101.57@-466.14,1084.65
  POWER3 w7.87: v1(-651.7,1723.18) -606.99,1678.47 -352.78,1678.47 -291.19,1616.88 -291.19,1589.02 -354.59,1525.62 -354.59,1456.14 -369.99,1440.75 -369.99,1397.31 -488.11,1279.19 -488.11,1209.34 -494.32,1203.13 -494.32,1154.62 -474.87,1135.18 v1(-474.87,1117.2)
  Bottom Layer 4 w7.87: CON201.5@-661.02,1786.42 -661.02,1735.7 v1@-650.71,1725.39 ; v1(-651.7,1723.18) -636.79,1708.27 -628.82,1708.27 R206.1@-622.42,1701.84
CAM_I2C_SDA: CON201.3 R205.1 U101.58@-418.9,1084.65 | length 1298.1
  Top Layer 1 w7.87: v1(-437.97,1048.08) -418.9,1067.15 U101.58@-418.9,1084.65 U101.58@-426.99,1076.55 ; U101.58@-427.36,1076.18 U101.58@-426.99,1076.55 ; -426.99,1061.73 U101.58@-426.99,1076.55 ; U101.58@-426.99,1079.22 U101.58@-426.99,1076.55
  POWER3 w7.87: v1(-702.66,1737.66) -629.61,1664.61 -358.52,1664.61 -305.05,1611.14 -305.05,1594.76 -368.45,1531.36 -368.45,1461.88 -383.85,1446.49 -383.85,1403.05 -501.97,1284.93 -501.97,1215.08 -508.18,1208.87 -508.18,1148.88 -494.69,1135.4 -494.69,1108.34 -437.97,1051.61 v1(-437.97,1048.08)
  Bottom Layer 4 w7.87: R205.1@-737.63,1706.72 v1@-703.6,1740.75 ; v1(-702.66,1737.66) -702.66,1740.28 -700.39,1742.54 CON201.3@-700.39,1786.42
CAM_MCLK: C213.2 CON201.13 R104.1 | length 118.8
  Bottom Layer 4 w7.87: R104.1@-506.13,1668.73 C213.2@-506.13,1702.63 -503.74,1705.02 -503.74,1786.22 CON201.13@-503.54,1786.42
CAM_PWDN: CON201.8 U101.81@-387.4,1153.54 | length 1054.5
  Top Layer 1 w7.87: v1(-474.56,1194.01) -472.3,1191.75 -446.91,1191.75 -414.29,1159.13 -392.99,1159.13 U101.81@-387.4,1153.54
  POWER3 w7.87: v1(-601.51,1735.58) -601.51,1707.02 -586.81,1692.33 -344.71,1692.33 -277.13,1624.75 -277.13,1583.48 -340.74,1519.88 -340.74,1450.4 -356.13,1435.01 -356.13,1391.57 -474.26,1273.45 -474.26,1194.31 v1(-474.56,1194.01)
  Bottom Layer 4 w7.87: v1@-601.77,1735.84 CON201.8@-601.77,1786.22
  Bottom Layer 4 w10: CON201.8@-601.97,1786.42 CON201.8@-601.77,1786.22 ; v1@-601.77,1735.84 v1(-601.51,1735.58)
CAM_SPI_CLK: C214.2 CON201.17 R102.1 | length 125.8
  Bottom Layer 4 w7.87: R102.1@-427.78,1662.78 C214.2@-427.78,1700.55 ; R102.1@-427.15,1661.78 R102.1@-427.15,1666 ; CON201.17@-424.8,1786.42 -424.8,1704.27 C214.2@-423.61,1703.07
CAM_SPI_D0: C215.2 R207.1 U101.55@-560.63,1084.65 | length 713.1
  Top Layer 1 w7.87: U101.55@-560.63,1084.65 -550.79,1094.49 -550.79,1117.13 v1(-549.89,1118.03)
  POWER3 w7.87: v1(-549.89,1118.03) -549.5,1118.42 -549.5,1132.52 -538.04,1143.98 -538.04,1218.2 -529.69,1226.56 -529.69,1296.41 -411.57,1414.53 -411.57,1457.97 -396.17,1473.36 -396.17,1557.86 v1(-365.37,1588.66)
  Bottom Layer 4 w7.87: R207.1@-380.3,1664.89 -379.83,1665.36 -340.59,1665.36 C215.2@-340.12,1665.83 -342.1,1663.85 -342.1,1648.3 -365.37,1625.02 v1(-365.37,1588.66)
CAM_SPI_D1: C216.2 R208.1 U101.56@-513.39,1084.64 | length 742.2
  Top Layer 1 w7.87: v1(-514.47,1117.04) -514.47,1085.73 U101.56@-513.39,1084.64
  POWER3 w7.87: v1(-514.47,1117.04) -516.73,1119.3 -516.73,1137.84 -522.04,1143.14 -522.04,1214.61 -515.83,1220.82 -515.83,1290.67 -397.71,1408.79 -397.71,1452.23 -382.31,1467.62 -382.31,1543.77 -324.81,1601.27 v1(-324.81,1602.95)
  Bottom Layer 4 w7.87: v1(-324.81,1602.95) -323.72,1601.86 -308.64,1601.86 -262.94,1647.56 -262.94,1663.84 C216.2@-261.69,1665.09 -263.16,1665.09 R208.1@-300.97,1665.09
CAM_VDD: C112.2 C211.1 CON201.4 TP101.1 U101.8@-820.47,1275.59 | length 750.6
  Top Layer 1 w15.75: U101.8@-820.47,1275.59 -787.55,1275.59 -787.55,1277.18 -776.77,1287.96 -776.77,1291.71 v1(-776.02,1292.46)
  Bottom Layer 4 w10: -723.39,1669.89 -721.06,1672.22 -682.04,1711.24 -680.71,1711.24 CON201.4@-680.71,1786.42 ; -723.35,1674.2 -681.99,1715.56 ; -721.77,1666.68 -721.06,1667.38 C211.1@-680.41,1708.03
  Bottom Layer 4 w15.75: C112.2@-794.79,1292.46 v1(-776.02,1292.46) ; v1(-776.02,1292.46) -776.02,1505.41 TP101.1@-769.01,1512.42 ; TP101.1@-771.49,1502.84 -765.46,1508.87 TP101.1@-769.01,1512.42 ; TP101.1@-765.46,1515.97 TP101.1@-769.01,1512.42 ; -721.06,1672.22 -721.06,1667.38 -721.06,1570.42 -774.03,1517.44 TP101.1@-769.01,1512.42
DBG_RXD: J202.32 U101.38@-426.77,1663.39 | length 1166
  Top Layer 1 w7.87: v1(-465.97,1589.12) -465.97,1589.92 -426.77,1629.12 U101.38@-426.77,1663.39
  POWER3 w7.87: J202.32@-995.08,853.94 J202.32@-963.39,853.94 -902.81,914.51 -902.81,1201.57 -730.78,1373.59 -564.03,1373.59 -555.62,1373.59 -473.37,1455.85 -473.37,1464.26 -473.37,1581.72 v1(-465.97,1589.12)
DBG_TXD: J202.31 U101.39@-470.08,1663.39 | length 1020.2
  Top Layer 1 w7.87: v1(-490.04,1615.13) -487.46,1615.13 -470.08,1632.5 U101.39@-470.08,1663.39
  POWER3 w7.87: J202.31@-963.39,953.94 -916.67,1000.65 -916.67,1207.31 -736.52,1387.45 -561.36,1387.45 -487.23,1461.59 -487.23,1612.31 -487.78,1612.87 v1(-490.04,1615.13)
